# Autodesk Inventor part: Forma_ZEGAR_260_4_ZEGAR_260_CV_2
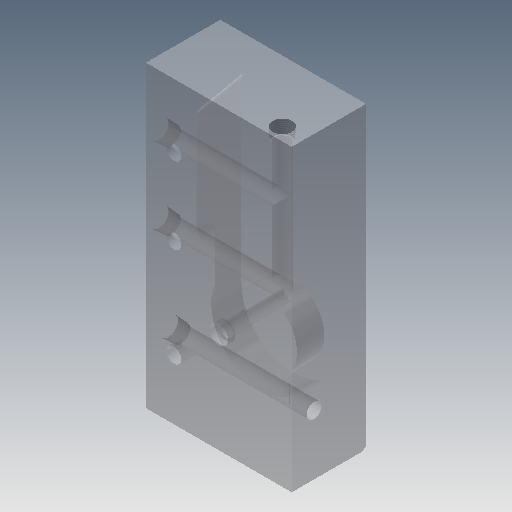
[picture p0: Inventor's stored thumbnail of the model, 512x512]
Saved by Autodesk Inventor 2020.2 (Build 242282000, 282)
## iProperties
Created: 2015-01
Part Number: Forma_ZEGAR_260_4_ZEGAR_260_CV_2
Material: Ogólny
Document SubType Name: Modeling
Designer: F.Stasiak
Density: 1 g/cm^3
Appearance: Domyślna
Catalog Web Link: www.expertbooks.pl
Manager: www.cadconsulting.pl
Company: Fabian Stasiak CAD Consulting
Author: F.Stasiak
Subject: Zbiór ćwiczeń. Autodesk Inventor 2020. Kurs Professional
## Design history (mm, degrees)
node "Forma_ZEGAR_260_4_ZEGAR_260_CV_Base"
feature "Rzeźbienie3"
feature "Rzeźbienie13"
feature "Gwint6" dims "d10" = 0, "d11" = 0
feature "Rzeźbienie14"
feature "Gwint7" dims "d12" = 0, "d13" = 0
feature "Rzeźbienie15"
feature "Gwint8" dims "d14" = 0, "d15" = 0
feature "Rzeźbienie16"
feature "Gwint9" dims "d16" = 0, "d17" = 0
feature "Rzeźbienie17"
feature "Rzeźbienie18"
feature "Rzeźbienie19"
feature "Bryła1::Forma_ZEGAR_260_4_ZEGAR_260_CV_Base"
tag "Bryła wyprowadzona1"
node "Bryła1"
feature "Forma_ZEGAR_260_4_ZEGAR_260_CV_Base_Bodies"
feature "Powierzchnia3"
body "Srf3"
feature "Powierzchnia13"
body "Srf13"
feature "Powierzchnia14"
body "Srf14"
feature "Powierzchnia15"
body "Srf15"
feature "Powierzchnia16"
body "Srf16"
feature "Powierzchnia17"
body "Srf17"
feature "Powierzchnia18"
body "Srf18"
feature "Powierzchnia19"
body "Srf19"
